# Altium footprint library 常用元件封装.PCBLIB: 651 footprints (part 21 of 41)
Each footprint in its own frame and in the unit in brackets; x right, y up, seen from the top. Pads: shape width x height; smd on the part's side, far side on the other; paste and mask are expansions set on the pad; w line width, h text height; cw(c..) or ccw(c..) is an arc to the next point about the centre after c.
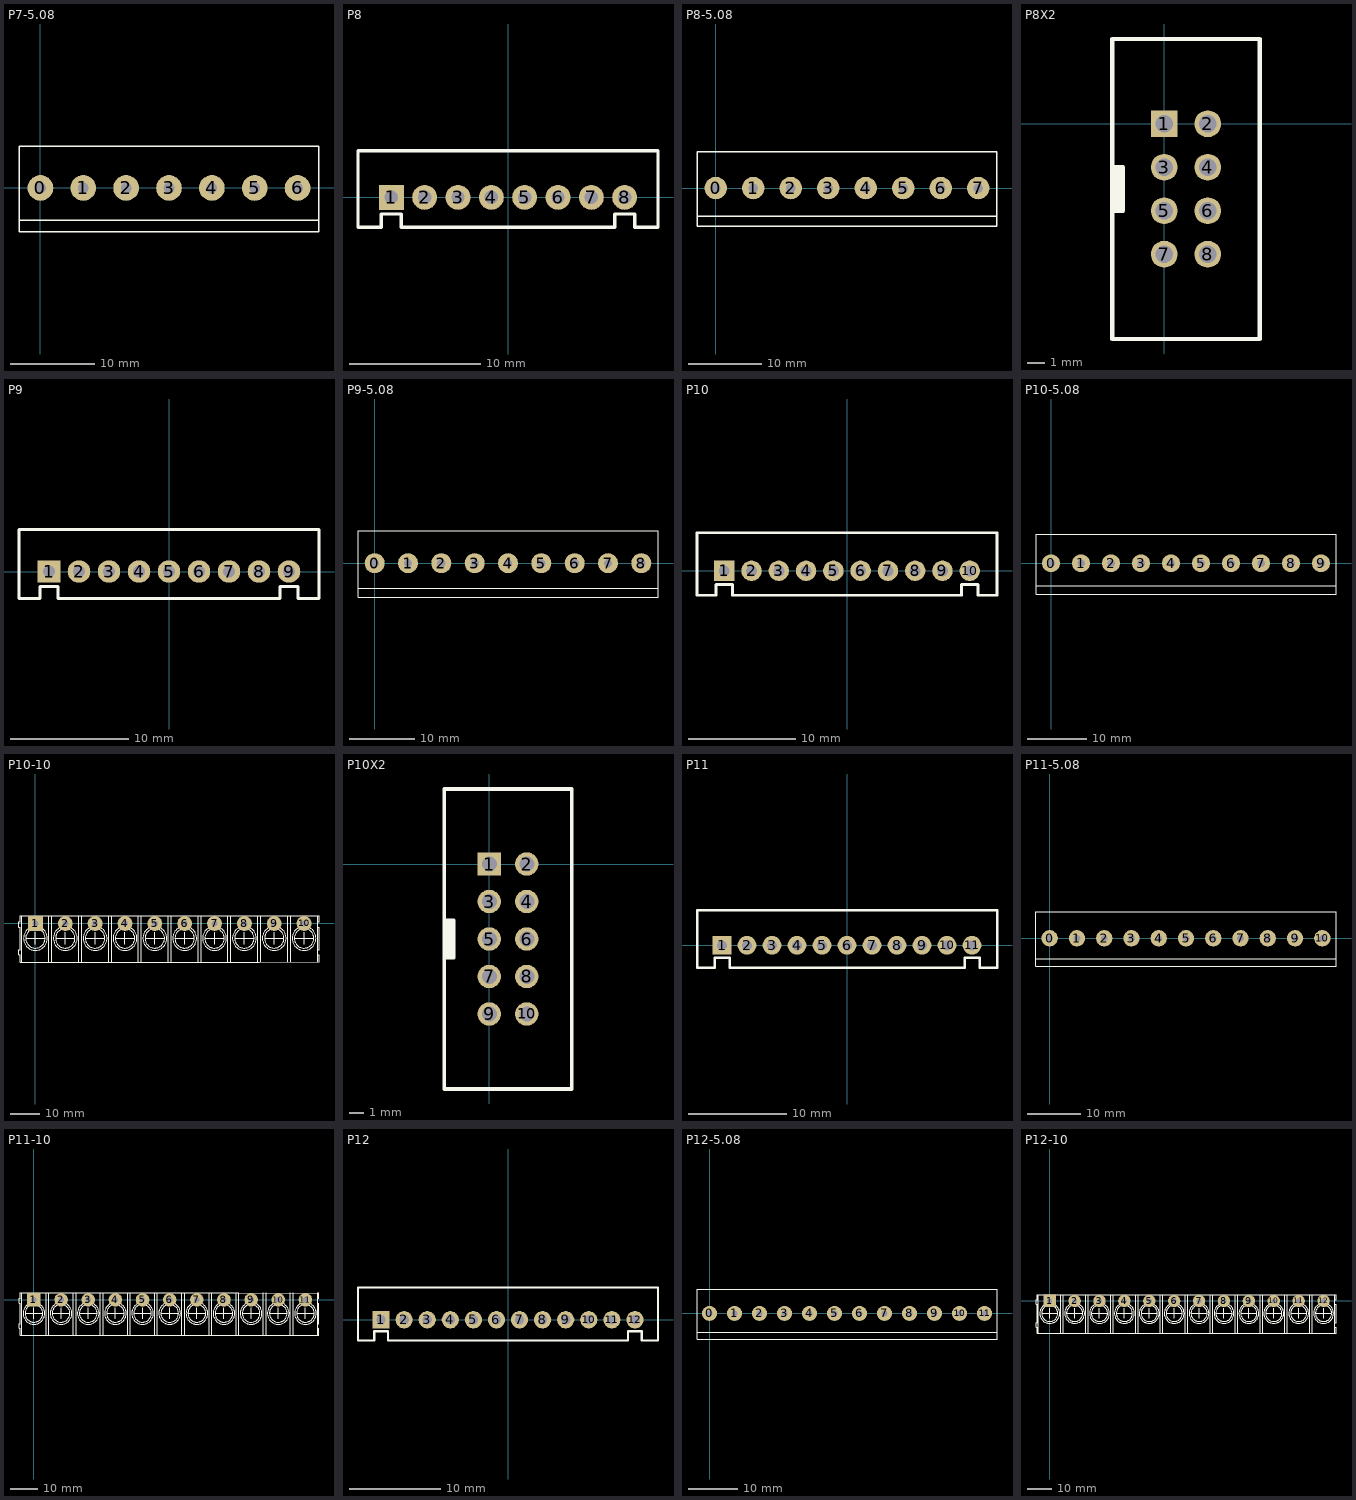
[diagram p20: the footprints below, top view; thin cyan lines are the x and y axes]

## P7-5.08 [mil]
height 543.31
pads (7):
  round 120 hole 50: 0(0,0) 1(200,0) 2(400,0) 3(600,0) 4(800,0) 5(1000,0) 6(1200,0)
TopOverlay:
  lines w6.69: -100,-150 1300,-150 ; -100,-205 -100,195 1300,195 1300,-205 -100,-205

## P8 [mil]
pads (8):
  rect 75x75 hole 40: 1(-350,0)
  round 75 hole 40: 2(-250,0) 3(-150,0) 4(-50,0) 5(50,0) 6(150,0) 7(250,0) 8(350,0)
TopOverlay:
  lines w10: -450,-90 -450,0 -450,140 450,140 450,-90 380,-90 380,-50 320,-50 320,-90 -320,-90 -320,-50 -380,-50 -380,-90 -450,-90

## P8-5.08 [mil]
height 543.31
pads (8):
  round 120 hole 50: 0(0,0) 1(200,0) 2(400,0) 3(600,0) 4(800,0) 5(1000,0) 6(1200,0) 7(1400,0)
TopOverlay:
  lines w6.69: -100,-150 1500,-150 ; -100,-205 -100,195 1500,195 1500,-205 -100,-205

## P8X2 [mm]
pads (8):
  rect 1.57x1.57 hole 1.016: 1(0,0)
  round 1.57 hole 1.016: 2(2.54,0) 3(0,-2.54) 4(2.54,-2.54) 5(0,-5.08) 6(2.54,-5.08) 7(0,-7.62) 8(2.54,-7.62)
TopOverlay:
  lines w0.254: -3.048,-2.54 -2.413,-2.54 -2.413,-5.08 -3.048,-5.08 -2.921,-4.953 -2.921,-2.54 ; -2.794,-5.08 -2.794,-2.54 ; -2.667,-5.08 -2.667,-2.54 ; -2.54,-4.953 -2.54,-2.54 ; -3.048,-12.573 5.588,-12.573 5.588,4.953 -3.048,4.953 -3.048,-12.573

## P9 [mil]
pads (9):
  rect 75x75 hole 40: 1(-400,0)
  round 75 hole 40: 2(-300,0) 3(-200,0) 4(-100,0) 5(0,0) 6(100,0) 7(200,0) 8(300,0) 9(400,0)
TopOverlay:
  lines w10: -500,-90 -430,-90 -430,-50 -370,-50 -370,-90 370,-90 370,-50 430,-50 430,-90 500,-90 500,-50 500,140 -500,140 -500,0 -500,-90

## P9-5.08 [mil]
height 543.31
pads (9):
  round 120 hole 50: 0(0,0) 1(200,0) 2(400,0) 3(600,0) 4(800,0) 5(1000,0) 6(1200,0) 7(1400,0) 8(1600,0)
TopOverlay:
  lines w6.69: -100,-150 1700,-150 ; -100,-205 -100,195 1700,195 1700,-205 -100,-205

## P10 [mil]
pads (10):
  rect 75x75 hole 40: 1(-450,0)
  round 75 hole 40: 2(-350,0) 3(-250,0) 4(-150,0) 5(-50,0) 6(50,0) 7(150,0) 8(250,0) 9(350,0) 10(450,0)
TopOverlay:
  lines w10: -550,-90 -480,-90 -480,-50 -420,-50 -420,-90 370,-90 420,-90 420,-50 480,-50 480,-90 550,-90 550,140 -550,140 -550,0 -550,-90

## P10-5.08 [mil]
height 543.31
pads (10):
  round 120 hole 50: 0(0,0) 1(200,0) 2(400,0) 3(600,0) 4(800,0) 5(1000,0) 6(1200,0) 7(1400,0) 8(1600,0) 9(1800,0)
TopOverlay:
  lines w6.69: -100,-150 1900,-150 ; -100,-205 -100,195 1900,195 1900,-205 -100,-205

## P10-10 [mm]
pads (10):
  rect 5x5 hole 2: 1(0,0)
  round 5 hole 2: 2(10,0) 3(20,0) 4(30,0) 5(40,0) 6(50,0) 7(60,0) 8(70,0) 9(80,0) 10(90,0)
TopOverlay:
  circle w0.254: c90,-5 r4
  circle w0.254: c90,-5 r3.26
  circle w0.254: c80,-5 r4
  circle w0.254: c80,-5 r3.26
  circle w0.254: c70,-5 r4
  circle w0.254: c70,-5 r3.26
  circle w0.254: c60,-5 r4
  circle w0.254: c60,-5 r3.26
  circle w0.254: c50,-5 r4
  circle w0.254: c50,-5 r3.26
  circle w0.254: c40,-5 r4
  circle w0.254: c40,-5 r3.26
  circle w0.254: c30,-5 r4
  circle w0.254: c30,-5 r3.26
  circle w0.254: c20,-5 r4
  circle w0.254: c20,-5 r3.26
  circle w0.254: c10,-5 r4
  circle w0.254: c10,-5 r3.26
  circle w0.254: c0,-5 r4
  circle w0.254: c0,-5 r3.26
  lines w0.254: -4.5,-13 -4.5,2.5 ; -3.25,-5 3.25,-5 ; 0,-7 0,-3 ; 4.5,-13 4.5,2.5 ; 5.5,-13 5.5,2.5 ; 6.75,-5 13.25,-5 ; 10,-7 10,-3 ; 14.5,-13 14.5,2.5 ; 15.5,-13 15.5,2.5 ; 16.75,-5 23.25,-5 ; 20,-7 20,-3 ; 24.5,-13 24.5,2.5 ; 25.5,-13 25.5,2.5 ; 26.75,-5 33.25,-5 ; 30,-7 30,-3 ; 34.5,-13 34.5,2.5 ; 35.5,-13 35.5,2.5 ; 36.75,-5 43.25,-5 ; 40,-7 40,-3 ; 44.5,-13 44.5,2.5 ; 45.5,-13 45.5,2.5 ; 46.75,-5 53.25,-5 ; 50,-7 50,-3 ; 54.5,-13 54.5,2.5 ; 55.5,-13 55.5,2.5 ; 56.75,-5 63.25,-5 ; 60,-7 60,-3 ; 64.5,-13 64.5,2.5 ; 65.5,-13 65.5,2.5 ; 66.75,-5 73.25,-5 ; 70,-7 70,-3 ; 74.5,-13 74.5,2.5 ; 75.5,-13 75.5,2.5 ; 76.75,-5 83.25,-5 ; 80,-7 80,-3 ; 84.5,-13 84.5,2.5 ; 85.5,-13 85.5,2.5 ; 86.75,-5 93.25,-5 ; 90,-7 90,-3 ; 94.5,-13 94.5,2.5 ; 94.9,-12.925 75,-13 35,-13 -5,-13 -5,-10.5 -5.5,-10.5 -5.5,-8.75 -5,-8.75 -5,-1.25 -5.5,-1.25 -5.5,0.5 -5,0.5 -5,2.5 35,2.5 75,2.5 94.975,2.55 ; 95,-13 95,-10.5 94.5,-10.5 94.5,-8.75 95,-8.75 95,-1.25 94.5,-1.25 94.5,0.5 95,0.5 95,2.5 ; 34.5,-10.5 34.5,-8.75 34.5,-10.5 ; 34.5,-1.25 34.5,0.5 34.5,-1.25 ; 74.5,-10.5 74.5,-8.75 74.5,-10.5 ; 74.5,-1.25 74.5,0.5 74.5,-1.25

## P10X2 [mm]
pads (10):
  rect 1.58x1.58 hole 1.016: 1(0,0)
  round 1.58 hole 1.016: 2(2.54,0) 3(0,-2.54) 4(2.54,-2.54) 5(0,-5.08) 6(2.54,-5.08) 7(0,-7.62) 8(2.54,-7.62) 9(0,-10.16) 10(2.54,-10.16)
TopOverlay:
  lines w0.254: -3.048,-6.35 -2.413,-6.35 -2.413,-3.81 -3.048,-3.81 ; -2.921,-6.35 -2.921,-3.81 ; -2.794,-6.35 -2.794,-3.81 ; -2.667,-6.35 -2.667,-3.81 ; -2.54,-6.35 -2.54,-3.81 ; -3.048,-15.24 -3.048,5.08 5.588,5.08 5.588,-15.24 -3.048,-15.24

## P11 [mil]
pads (11):
  rect 75x75 hole 40: 1(-500,0)
  round 75 hole 40: 2(-400,0) 3(-300,0) 4(-200,0) 5(-100,0) 6(0,0) 7(100,0) 8(200,0) 9(300,0) 10(400,0) 11(500,0)
TopOverlay:
  lines w10: -600,-90 -530,-90 -530,-50 -470,-50 -470,-90 470,-90 470,-50 530,-50 530,-90 600,-90 600,140 -600,140 -600,0 -600,-90

## P11-5.08 [mil]
height 543.31
pads (11):
  round 120 hole 50: 0(0,0) 1(200,0) 2(400,0) 3(600,0) 4(800,0) 5(1000,0) 6(1200,0) 7(1400,0) 8(1600,0) 9(1800,0) 10(2000,0)
TopOverlay:
  lines w6.69: -100,-150 2100,-150 ; -100,-205 2100,-205 2100,195 -100,195 -100,-205

## P11-10 [mm]
pads (11):
  rect 5x5 hole 2: 1(0,0)
  round 5 hole 2: 2(10,0) 3(20,0) 4(30,0) 5(40,0) 6(50,0) 7(60,0) 8(70,0) 9(80,0) 10(90,0) 11(100,0)
TopOverlay:
  circle w0.254: c100,-5 r4
  circle w0.254: c100,-5 r3.26
  circle w0.254: c90,-5 r4
  circle w0.254: c90,-5 r3.26
  circle w0.254: c80,-5 r4
  circle w0.254: c80,-5 r3.26
  circle w0.254: c70,-5 r4
  circle w0.254: c70,-5 r3.26
  circle w0.254: c60,-5 r4
  circle w0.254: c60,-5 r3.26
  circle w0.254: c50,-5 r4
  circle w0.254: c50,-5 r3.26
  circle w0.254: c40,-5 r4
  circle w0.254: c40,-5 r3.26
  circle w0.254: c30,-5 r4
  circle w0.254: c30,-5 r3.26
  circle w0.254: c20,-5 r4
  circle w0.254: c20,-5 r3.26
  circle w0.254: c10,-5 r4
  circle w0.254: c10,-5 r3.26
  circle w0.254: c0,-5 r4
  circle w0.254: c0,-5 r3.26
  lines w0.254: -4.5,-13 -4.5,2.5 ; -3.25,-5 3.25,-5 ; 0,-7 0,-3 ; 4.5,-13 4.5,2.5 ; 5.5,-13 5.5,2.5 ; 6.75,-5 13.25,-5 ; 10,-7 10,-3 ; 14.5,-13 14.5,2.5 ; 15.5,-13 15.5,2.5 ; 16.75,-5 23.25,-5 ; 20,-7 20,-3 ; 24.5,-13 24.5,2.5 ; 25.5,-13 25.5,2.5 ; 26.75,-5 33.25,-5 ; 30,-7 30,-3 ; 34.5,-13 34.5,2.5 ; 35.5,-13 35.5,2.5 ; 36.75,-5 43.25,-5 ; 40,-7 40,-3 ; 44.5,-13 44.5,2.5 ; 45.5,-13 45.5,2.5 ; 46.75,-5 53.25,-5 ; 50,-7 50,-3 ; 54.5,-13 54.5,2.5 ; 55.5,-13 55.5,2.5 ; 56.75,-5 63.25,-5 ; 60,-7 60,-3 ; 64.5,-13 64.5,2.5 ; 65.5,-13 65.5,2.5 ; 66.75,-5 73.25,-5 ; 70,-7 70,-3 ; 74.5,-13 74.5,2.5 ; 75.5,-13 75.5,2.5 ; 76.75,-5 83.25,-5 ; 80,-7 80,-3 ; 84.5,-13 84.5,2.5 ; 85.5,-13 85.5,2.5 ; 86.75,-5 93.25,-5 ; 90,-7 90,-3 ; 94.5,-13 94.5,2.5 ; 95.5,-13 95.5,2.5 ; 96.75,-5 103.25,-5 ; 100,-7 100,-3 ; 104.5,-13 104.5,2.5 ; 105,2.4 75,2.5 35,2.5 -5,2.5 -5,0.5 -5.5,0.5 -5.5,-1.25 -5,-1.25 -5,-8.75 -5.5,-8.75 -5.5,-10.5 -5,-10.5 -5,-13 35,-13 75,-13 105,-13 105,-10.5 104.5,-10.5 104.5,-8.75 105,-8.75 105,-1.25 104.5,-1.25 104.5,0.5 105,0.5 105,2.5 ; 34.5,-10.5 34.5,-8.75 34.5,-10.5 ; 34.5,-1.25 34.5,0.5 34.5,-1.25 ; 74.5,-10.5 74.5,-8.75 74.5,-10.5 ; 74.5,-1.25 74.5,0.5 74.5,-1.25

## P12 [mil]
pads (12):
  rect 75x75 hole 40: 1(-550,0)
  round 75 hole 40: 2(-450,0) 3(-350,0) 4(-250,0) 5(-150,0) 6(-50,0) 7(50,0) 8(150,0) 9(250,0) 10(350,0) 11(450,0) 12(550,0)
TopOverlay:
  lines w10: -650,-90 -650,0 -650,140 650,140 650,-90 580,-90 580,-50 520,-50 520,-90 -520,-90 -520,-50 -580,-50 -580,-90 -650,-90

## P12-5.08 [mil]
height 543.31
pads (12):
  round 120 hole 50: 0(0,0) 1(200,0) 2(400,0) 3(600,0) 4(800,0) 5(1000,0) 6(1200,0) 7(1400,0) 8(1600,0) 9(1800,0) 10(2000,0) 11(2200,0)
TopOverlay:
  lines w6.69: -100,-150 2300,-150 ; -100,-205 2300,-205 2300,195 -100,195 -100,-205

## P12-10 [mm]
pads (12):
  rect 5x5 hole 2: 1(0,0)
  round 5 hole 2: 2(10,0) 3(20,0) 4(30,0) 5(40,0) 6(50,0) 7(60,0) 8(70,0) 9(80,0) 10(90,0) 11(100,0) 12(110,0)
TopOverlay:
  circle w0.254: c110,-5 r4
  circle w0.254: c110,-5 r3.26
  circle w0.254: c100,-5 r4
  circle w0.254: c100,-5 r3.26
  circle w0.254: c90,-5 r4
  circle w0.254: c90,-5 r3.26
  circle w0.254: c80,-5 r4
  circle w0.254: c80,-5 r3.26
  circle w0.254: c70,-5 r4
  circle w0.254: c70,-5 r3.26
  circle w0.254: c60,-5 r4
  circle w0.254: c60,-5 r3.26
  circle w0.254: c50,-5 r4
  circle w0.254: c50,-5 r3.26
  circle w0.254: c40,-5 r4
  circle w0.254: c40,-5 r3.26
  circle w0.254: c30,-5 r4
  circle w0.254: c30,-5 r3.26
  circle w0.254: c20,-5 r4
  circle w0.254: c20,-5 r3.26
  circle w0.254: c10,-5 r4
  circle w0.254: c10,-5 r3.26
  circle w0.254: c0,-5 r4
  circle w0.254: c0,-5 r3.26
  lines w0.254: -4.5,-13 -4.5,2.5 ; -3.25,-5 3.25,-5 ; 0,-7 0,-3 ; 4.5,-13 4.5,2.5 ; 5.5,-13 5.5,2.5 ; 6.75,-5 13.25,-5 ; 10,-7 10,-3 ; 14.5,-13 14.5,2.5 ; 15.5,-13 15.5,2.5 ; 16.75,-5 23.25,-5 ; 20,-7 20,-3 ; 24.5,-13 24.5,2.5 ; 25.5,-13 25.5,2.5 ; 26.75,-5 33.25,-5 ; 30,-7 30,-3 ; 34.5,-13 34.5,2.5 ; 35.5,-13 35.5,2.5 ; 36.75,-5 43.25,-5 ; 40,-7 40,-3 ; 44.5,-13 44.5,2.5 ; 45.5,-13 45.5,2.5 ; 46.75,-5 53.25,-5 ; 50,-7 50,-3 ; 54.5,-13 54.5,2.5 ; 55.5,-13 55.5,2.5 ; 56.75,-5 63.25,-5 ; 60,-7 60,-3 ; 64.5,-13 64.5,2.5 ; 65.5,-13 65.5,2.5 ; 66.75,-5 73.25,-5 ; 70,-7 70,-3 ; 74.5,-13 74.5,2.5 ; 75.5,-13 75.5,2.5 ; 76.75,-5 83.25,-5 ; 80,-7 80,-3 ; 84.5,-13 84.5,2.5 ; 85.5,-13 85.5,2.5 ; 86.75,-5 93.25,-5 ; 90,-7 90,-3 ; 94.5,-13 94.5,2.5 ; 95.5,-13 95.5,2.5 ; 96.75,-5 103.25,-5 ; 100,-7 100,-3 ; 104.5,-13 104.5,2.5 ; 105.5,-13 105.5,2.5 ; 106.75,-5 113.25,-5 ; 110,-7 110,-3 ; 114.5,-13 114.5,2.5 ; -5.5,-10.5 -5.5,-8.75 -5,-8.75 -5,-1.25 -5.5,-1.25 -5.5,0.5 -5,0.5 -5,2.5 35,2.5 75,2.5 115,2.5 115,0.5 114.5,0.5 114.5,-1.25 115,-1.25 115,-8.75 114.5,-8.75 114.5,-10.5 115,-10.5 115,-13 75,-13 35,-13 -5,-13 -5,-10.5 -5.5,-10.5 ; 34.5,-10.5 34.5,-8.75 34.5,-10.5 ; 34.5,-1.25 34.5,0.5 34.5,-1.25 ; 74.5,-10.5 74.5,-8.75 74.5,-10.5 ; 74.5,-1.25 74.5,0.5 74.5,-1.25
